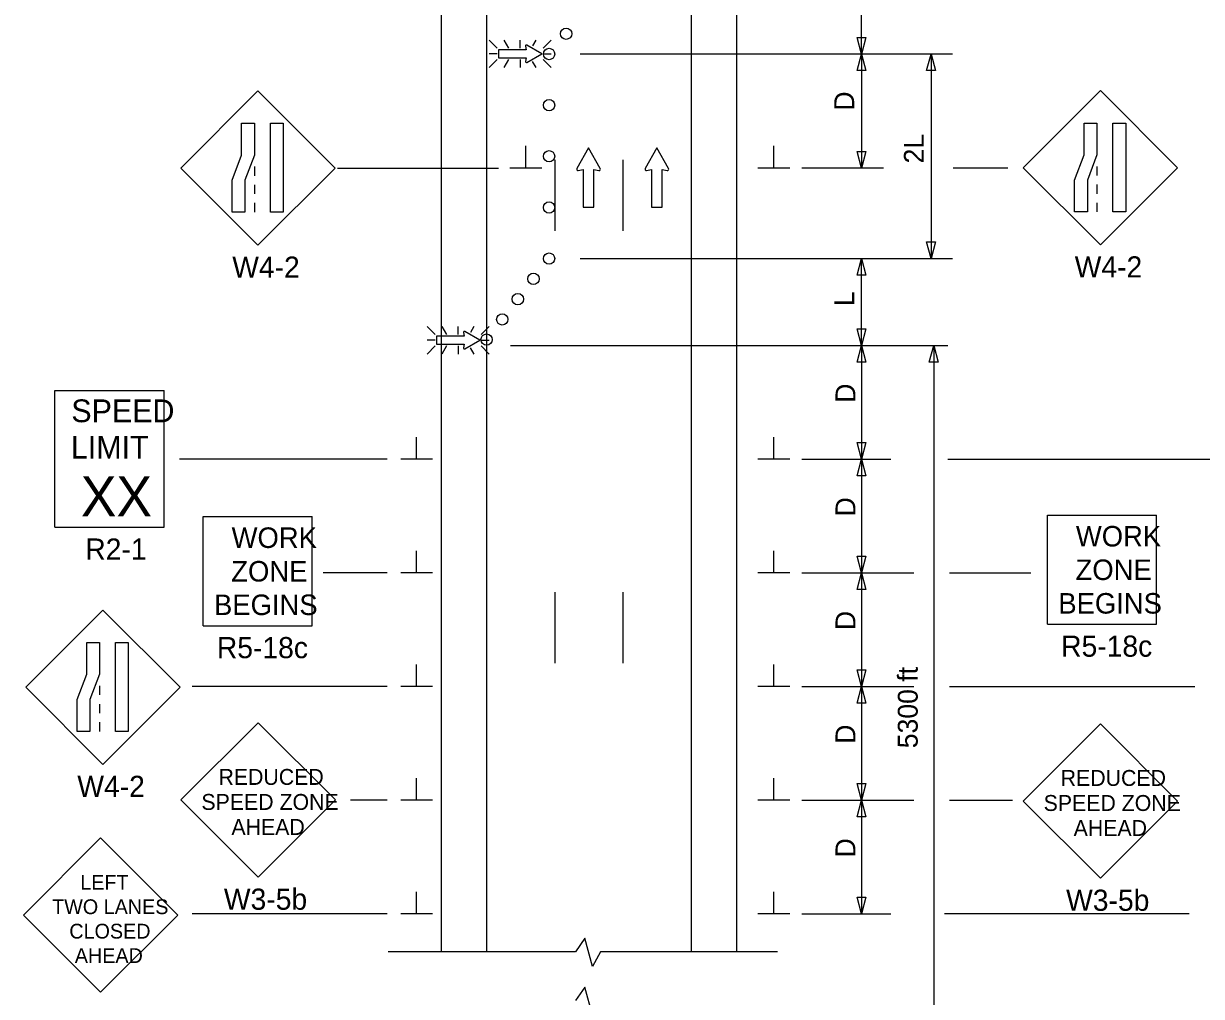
# Model space of a CAD drawing. Extents: x 16590 to 19504, y 5703 to 6974.
# Drawn here: x 17753.9 to 18168.7, y 6275.8 to 6618.1 of the extents above; entities that cross this region are included whole.
import ezdxf

# ---------------------------------------------------------------- set-up
doc = ezdxf.new("R2010")
doc.units = 0
for name, color, linetype in [('ALI_LEGAL_EX', 7, 'Continuous'), ('MT_SCRATCH_LEVEL_E', 7, 'Continuous'), ('PAVT_EDGE_EX', 7, 'Continuous'), ('TRAFFIC_SIGNS_PR', 7, 'Continuous'), ('TYPICAL_TEXT_DIMEN_PR', 7, 'Continuous')]:
    doc.layers.add(name, color=color, linetype=linetype)

msp = doc.modelspace()

# ---------------------------------------------------------------- linework, layer by layer
at = {"layer": 'ALI_LEGAL_EX'}
for points in [[(17940.96, 6570.12), (17940.96, 6545.12)], [(17964.96, 6570.12), (17964.96, 6545.12)], [(17940.96, 6418.06), (17940.96, 6393.06)], [(17964.96, 6418.06), (17964.96, 6393.06)]]:
    msp.add_lwpolyline(points, dxfattribs=at)
at = {"layer": 'MT_SCRATCH_LEVEL_E'}
for p, q in [((17952.86, 6574.33), (17948.75, 6567.09)), ((17957.01, 6567.09), (17952.86, 6574.33)), ((17976.91, 6574.33), (17972.8, 6567.09)), ((17981.06, 6567.09), (17976.91, 6574.33)), ((17949.23, 6566.4), (17951.01, 6566.72)), ((17951.01, 6566.72), (17951.01, 6553.46)), ((17954.75, 6553.46), (17954.75, 6566.72)), ((17954.75, 6566.72), (17956.53, 6566.4)), ((17973.28, 6566.4), (17975.06, 6566.72)), ((17975.06, 6566.72), (17975.06, 6553.46)), ((17978.8, 6553.46), (17978.8, 6566.72)), ((17978.8, 6566.72), (17980.58, 6566.4)), ((17951.01, 6553.46), (17954.75, 6553.46)), ((17975.06, 6553.46), (17978.8, 6553.46))]:
    msp.add_line(p, q, dxfattribs=at)
for centre, start, end in [((17949.16, 6566.86), 150.4248, 279.9638), ((17956.6, 6566.86), 260.0362, 29.7731), ((17973.21, 6566.86), 150.4248, 279.9638), ((17980.65, 6566.86), 260.0362, 29.7731)]:
    msp.add_arc(centre, 0.463, start, end, dxfattribs=at)
at = {"layer": 'PAVT_EDGE_EX'}
for p, q in [((17900.96, 6925.33), (17900.96, 6504.84)), ((17916.96, 6925.33), (17916.96, 6504.84)), ((17988.96, 6925.33), (17988.96, 6504.84)), ((18004.96, 6925.33), (18004.96, 6504.84)), ((17900.96, 6504.84), (17900.96, 6291.41)), ((17916.96, 6504.84), (17916.96, 6291.41)), ((17988.96, 6504.84), (17988.96, 6291.41)), ((18004.96, 6504.84), (18004.96, 6291.41))]:
    msp.add_line(p, q, dxfattribs=at)
at = {"layer": 'TRAFFIC_SIGNS_PR'}
for p, q in [((17920.73, 6609.5), (17917.91, 6612.32)), ((17923.03, 6612.32), (17924.66, 6609.5)), ((17928.82, 6609.5), (17928.82, 6612.32)), ((17934.29, 6612.32), (17933.08, 6610.23)), ((17939.72, 6612.32), (17936.9, 6609.5)), ((17920.73, 6607.47), (17917.91, 6607.47)), ((17936.9, 6607.47), (17939.72, 6607.47)), ((17920.73, 6605.44), (17917.91, 6602.62)), ((17924.68, 6605.44), (17923.05, 6602.62)), ((17928.82, 6605.44), (17928.82, 6602.62)), ((17933, 6604.8), (17934.26, 6602.62)), ((17939.72, 6602.62), (17936.9, 6605.44)), ((17836.44, 6594.43), (17809.29, 6567.28)), ((17863.59, 6567.28), (17836.44, 6594.43)), ((18133.1, 6594.51), (18105.94, 6567.36)), ((18160.25, 6567.36), (18133.1, 6594.51)), ((17809.29, 6567.28), (17836.44, 6540.13)), ((17835.19, 6567.77), (17835.19, 6564.57)), ((17836.44, 6540.13), (17863.59, 6567.28)), ((18105.94, 6567.36), (18133.1, 6540.2)), ((18131.85, 6567.85), (18131.85, 6564.65)), ((18133.1, 6540.2), (18160.25, 6567.36)), ((17835.19, 6561.37), (17835.19, 6558.17)), ((18131.85, 6561.45), (18131.85, 6558.25)), ((17835.19, 6554.97), (17835.19, 6551.77)), ((18131.85, 6555.05), (18131.85, 6551.85)), ((17898.89, 6508.72), (17896.07, 6511.54)), ((17901.19, 6511.53), (17902.82, 6508.72)), ((17906.98, 6508.72), (17906.98, 6511.53)), ((17912.44, 6511.53), (17911.24, 6509.44)), ((17917.88, 6511.53), (17915.06, 6508.72)), ((17898.89, 6506.68), (17896.07, 6506.68)), ((17898.89, 6504.65), (17896.07, 6501.83)), ((17902.84, 6504.65), (17901.21, 6501.83)), ((17906.98, 6504.65), (17906.98, 6501.83)), ((17911.16, 6504.02), (17912.42, 6501.83)), ((17915.06, 6506.68), (17917.88, 6506.68)), ((17917.88, 6501.83), (17915.06, 6504.65)), ((17764.96, 6488.98), (17803.41, 6488.98)), ((17764.96, 6440.92), (17764.96, 6488.98)), ((17803.41, 6440.92), (17803.41, 6488.98)), ((17817.18, 6406.22), (17817.18, 6444.62)), ((17817.18, 6444.62), (17855.58, 6444.62)), ((17855.58, 6406.22), (17855.58, 6444.62)), ((18114.47, 6406.74), (18114.47, 6445.14)), ((18114.47, 6445.14), (18152.87, 6445.14)), ((18152.87, 6406.74), (18152.87, 6445.14)), ((17764.96, 6440.92), (17803.41, 6440.92)), ((17781.89, 6411.7), (17754.73, 6384.55)), ((17809.04, 6384.55), (17781.89, 6411.7)), ((17817.18, 6406.22), (17855.58, 6406.22)), ((18114.47, 6406.74), (18152.87, 6406.74)), ((17754.73, 6384.55), (17781.89, 6357.4)), ((17780.64, 6385.04), (17780.64, 6381.84)), ((17781.89, 6357.4), (17809.04, 6384.55)), ((17780.64, 6378.64), (17780.64, 6375.44)), ((17780.64, 6372.24), (17780.64, 6369.04)), ((17836.52, 6372.08), (17809.33, 6344.89)), ((17863.7, 6344.89), (17836.52, 6372.08)), ((18133.07, 6371.7), (18105.89, 6344.52)), ((18160.26, 6344.52), (18133.07, 6371.7)), ((17809.33, 6344.89), (17836.52, 6317.7)), ((17836.52, 6317.7), (17863.7, 6344.89)), ((18105.89, 6344.52), (18133.07, 6317.33)), ((18133.07, 6317.33), (18160.26, 6344.52)), ((17781.07, 6331.54), (17753.92, 6304.38)), ((17808.22, 6304.38), (17781.07, 6331.54)), ((17753.92, 6304.38), (17781.07, 6277.23)), ((17781.07, 6277.23), (17808.22, 6304.38))]:
    msp.add_line(p, q, dxfattribs=at)
for points in [[(17930.64, 6610.15), (17930.87, 6608.86), (17921.15, 6608.86), (17921.15, 6606.11), (17930.87, 6606.11), (17930.64, 6604.81)], [(17931.14, 6604.46), (17936.45, 6607.47), (17931.14, 6610.51)], [(17908.8, 6509.36), (17909.03, 6508.07), (17899.31, 6508.07), (17899.31, 6505.32), (17909.03, 6505.32), (17908.8, 6504.02)], [(17909.3, 6503.67), (17914.61, 6506.68), (17909.3, 6509.72)]]:
    msp.add_lwpolyline(points, dxfattribs=at)
for points in [[(17835.19, 6583.02), (17835.19, 6571.83), (17831.85, 6562.95), (17831.85, 6551.77), (17827.36, 6551.77), (17827.36, 6562.95), (17830.7, 6571.83), (17830.7, 6583.02)], [(17845.33, 6583.02), (17845.33, 6551.77), (17840.84, 6551.77), (17840.84, 6583.02)], [(18131.85, 6583.09), (18131.85, 6571.91), (18128.51, 6563.03), (18128.51, 6551.85), (18124.01, 6551.85), (18124.01, 6563.03), (18127.36, 6571.91), (18127.36, 6583.09)], [(18141.99, 6583.09), (18141.99, 6551.85), (18137.49, 6551.85), (18137.49, 6583.09)], [(17780.64, 6400.29), (17780.64, 6389.11), (17777.3, 6380.22), (17777.3, 6369.04), (17772.8, 6369.04), (17772.8, 6380.22), (17776.15, 6389.11), (17776.15, 6400.29)], [(17790.78, 6400.29), (17790.78, 6369.04), (17786.28, 6369.04), (17786.28, 6400.29)]]:
    msp.add_lwpolyline(points, close=True, dxfattribs=at)
for centre in [(17944.96, 6614.54), (17938.96, 6607.4), (17938.96, 6589.4), (17938.96, 6571.4), (17938.96, 6553.4), (17938.96, 6535.4), (17933.46, 6528.27), (17927.96, 6521.14), (17922.47, 6514.01), (17916.97, 6506.89)]:
    msp.add_circle(centre, 2, dxfattribs=at)
for centre, start, end in [((17930.98, 6610.21), 61.4833, 189.9593), ((17930.98, 6604.76), 170.7308, 298.8916), ((17909.14, 6509.42), 61.4833, 189.9593), ((17909.14, 6503.97), 170.7308, 298.8916)]:
    msp.add_arc(centre, 0.341, start, end, dxfattribs=at)
at = {"layer": 'TYPICAL_TEXT_DIMEN_PR'}
for p, q in [((18048.96, 6607.4), (18048.96, 6637.96)), ((18048.96, 6607.4), (18047.39, 6613.26)), ((18047.39, 6613.26), (18048.96, 6613.26)), ((18048.96, 6613.26), (18050.53, 6613.26)), ((18050.53, 6613.26), (18048.96, 6607.4)), ((18081, 6607.4), (17949.86, 6607.4)), ((18047.39, 6601.54), (18048.96, 6607.4)), ((18048.96, 6607.4), (18048.96, 6567.27)), ((18048.96, 6607.4), (18050.53, 6601.54)), ((18071.9, 6601.54), (18073.47, 6607.4)), ((18073.47, 6607.4), (18075.04, 6601.54)), ((18073.47, 6607.4), (18073.47, 6535.4)), ((18048.96, 6601.54), (18047.39, 6601.54)), ((18050.53, 6601.54), (18048.96, 6601.54)), ((18073.47, 6601.54), (18071.9, 6601.54)), ((18075.04, 6601.54), (18073.47, 6601.54)), ((17930.81, 6567.27), (17930.81, 6575.06)), ((18018.08, 6567.27), (18018.08, 6575.06)), ((18048.96, 6567.27), (18047.39, 6573.13)), ((18047.39, 6573.13), (18048.96, 6573.13)), ((18048.96, 6573.13), (18050.53, 6573.13)), ((18050.53, 6573.13), (18048.96, 6567.27)), ((17864.45, 6567.27), (17921.15, 6567.27)), ((17936.43, 6567.27), (17925.18, 6567.27)), ((18023.71, 6567.27), (18012.46, 6567.27)), ((18056.71, 6567.27), (18027.96, 6567.27)), ((18100.5, 6567.27), (18081.25, 6567.27)), ((18073.47, 6562.27), (18073.47, 6558.5)), ((18073.47, 6535.4), (18071.9, 6541.26)), ((18071.9, 6541.26), (18073.47, 6541.26)), ((18073.47, 6541.26), (18075.04, 6541.26)), ((18075.04, 6541.26), (18073.47, 6535.4)), ((17949.86, 6535.4), (18081, 6535.4)), ((18047.39, 6529.54), (18048.96, 6535.4)), ((18048.96, 6504.84), (18048.96, 6535.4)), ((18048.96, 6535.4), (18050.53, 6529.54)), ((18048.96, 6529.54), (18047.39, 6529.54)), ((18050.53, 6529.54), (18048.96, 6529.54)), ((18048.96, 6504.84), (18047.39, 6510.7)), ((18047.39, 6510.7), (18048.96, 6510.7)), ((18048.96, 6510.7), (18050.53, 6510.7)), ((18050.53, 6510.7), (18048.96, 6504.84)), ((17925.35, 6504.84), (18079.39, 6504.84)), ((17925.35, 6504.84), (18079.39, 6504.84)), ((18047.39, 6498.97), (18048.96, 6504.84)), ((18048.96, 6504.84), (18048.96, 6464.84)), ((18048.96, 6504.84), (18050.53, 6498.97)), ((18072.82, 6498.97), (18074.39, 6504.84)), ((18074.39, 6504.84), (18075.96, 6498.97)), ((18074.39, 6504.84), (18074.39, 6229.16)), ((18048.96, 6498.97), (18047.39, 6498.97)), ((18050.53, 6498.97), (18048.96, 6498.97)), ((18074.39, 6498.97), (18072.82, 6498.97)), ((18075.96, 6498.97), (18074.39, 6498.97)), ((17892.33, 6464.83), (17892.33, 6472.61)), ((18018.08, 6464.83), (18018.08, 6472.61)), ((18048.96, 6464.84), (18047.39, 6470.7)), ((18047.39, 6470.7), (18048.96, 6470.7)), ((18048.96, 6470.7), (18050.53, 6470.7)), ((18050.53, 6470.7), (18048.96, 6464.84)), ((17881.91, 6464.84), (17808.8, 6464.84)), ((17897.96, 6464.83), (17886.71, 6464.83)), ((18023.71, 6464.83), (18012.46, 6464.83)), ((18027.96, 6464.84), (18059.27, 6464.84)), ((18047.39, 6458.97), (18048.96, 6464.84)), ((18048.96, 6464.84), (18048.96, 6424.84)), ((18048.96, 6464.84), (18050.53, 6458.97)), ((18079.39, 6464.84), (18174.5, 6464.84)), ((18048.96, 6458.97), (18047.39, 6458.97)), ((18050.53, 6458.97), (18048.96, 6458.97)), ((17892.33, 6424.83), (17892.33, 6432.61)), ((18018.08, 6424.83), (18018.08, 6432.61)), ((18048.96, 6424.84), (18047.39, 6430.7)), ((18047.39, 6430.7), (18048.96, 6430.7)), ((18048.96, 6430.7), (18050.53, 6430.7)), ((18050.53, 6430.7), (18048.96, 6424.84)), ((17881.91, 6424.84), (17859.38, 6424.84)), ((17897.96, 6424.83), (17886.71, 6424.83)), ((18023.71, 6424.83), (18012.46, 6424.83)), ((18027.96, 6424.84), (18067.4, 6424.84)), ((18047.39, 6418.97), (18048.96, 6424.84)), ((18048.96, 6424.84), (18048.96, 6384.84)), ((18048.96, 6424.84), (18050.53, 6418.97)), ((18079.94, 6424.84), (18108.56, 6424.84)), ((18048.96, 6418.97), (18047.39, 6418.97)), ((18050.53, 6418.97), (18048.96, 6418.97)), ((17892.33, 6384.83), (17892.33, 6392.61)), ((18018.08, 6384.83), (18018.08, 6392.61)), ((18048.96, 6384.84), (18047.39, 6390.7)), ((18047.39, 6390.7), (18048.96, 6390.7)), ((18048.96, 6390.7), (18050.53, 6390.7)), ((18050.53, 6390.7), (18048.96, 6384.84)), ((17881.91, 6384.84), (17813.3, 6384.84)), ((17897.96, 6384.83), (17886.71, 6384.83)), ((18023.71, 6384.83), (18012.46, 6384.83)), ((18027.96, 6384.84), (18067.4, 6384.84)), ((18047.39, 6378.97), (18048.96, 6384.84)), ((18048.96, 6384.84), (18048.96, 6344.84)), ((18048.96, 6384.84), (18050.53, 6378.97)), ((18079.94, 6384.84), (18166.36, 6384.84)), ((18048.96, 6378.97), (18047.39, 6378.97)), ((18050.53, 6378.97), (18048.96, 6378.97)), ((17892.33, 6344.83), (17892.33, 6352.61)), ((18018.08, 6344.83), (18018.08, 6352.61)), ((18048.96, 6344.84), (18047.39, 6350.7)), ((18047.39, 6350.7), (18048.96, 6350.7)), ((18048.96, 6350.7), (18050.53, 6350.7)), ((18050.53, 6350.7), (18048.96, 6344.84)), ((17881.91, 6344.84), (17869.02, 6344.84)), ((17897.96, 6344.83), (17886.71, 6344.83)), ((18023.71, 6344.83), (18012.46, 6344.83)), ((18027.96, 6344.84), (18067.4, 6344.84)), ((18047.39, 6338.97), (18048.96, 6344.84)), ((18048.96, 6344.84), (18048.96, 6304.84)), ((18048.96, 6344.84), (18050.53, 6338.97)), ((18079.94, 6344.84), (18102.1, 6344.84)), ((18048.96, 6338.97), (18047.39, 6338.97)), ((18050.53, 6338.97), (18048.96, 6338.97)), ((17892.33, 6304.83), (17892.33, 6312.61)), ((18018.08, 6304.83), (18018.08, 6312.61)), ((18048.96, 6304.84), (18047.39, 6310.7)), ((18047.39, 6310.7), (18048.96, 6310.7)), ((18048.96, 6310.7), (18050.53, 6310.7)), ((18050.53, 6310.7), (18048.96, 6304.84)), ((17881.91, 6304.84), (17813.3, 6304.84)), ((17897.96, 6304.83), (17886.71, 6304.83)), ((18023.71, 6304.83), (18012.46, 6304.83)), ((18027.96, 6304.84), (18059.27, 6304.84)), ((18164.29, 6304.84), (18078.14, 6304.84)), ((17951.56, 6296.21), (17948.31, 6291.41)), ((17954.3, 6286.27), (17951.56, 6296.21)), ((17948.31, 6291.41), (17882.36, 6291.41)), ((17957.05, 6291.41), (17954.3, 6286.27)), ((18019.38, 6291.41), (17957.05, 6291.41)), ((17951.56, 6279.07), (17948.31, 6274.27)), ((17954.3, 6269.13), (17951.56, 6279.07))]:
    msp.add_line(p, q, dxfattribs=at)

# ---------------------------------------------------------------- texts
at = {"layer": 'TRAFFIC_SIGNS_PR'}
for s, height, p in [('W4-2', 7.44, (17827.4, 6528.69)), ('W4-2', 7.44, (18124.05, 6528.76)), ('SPEED', 8.01, (17770.74, 6477.83)), ('LIMIT', 8.01, (17770.58, 6465.01)), ('XX', 14.048, (17774.09, 6444.68)), ('WORK', 7.217, (18124.46, 6434.1)), ('R2-1', 7.449, (17775.65, 6429.46)), ('WORK', 7.217, (17827.18, 6433.58)), ('ZONE', 7.217, (17827.06, 6421.77)), ('ZONE', 7.217, (18124.35, 6422.29)), ('BEGINS', 7.217, (17820.99, 6409.96)), ('BEGINS', 7.217, (18118.28, 6410.48)), ('R5-18c', 7.44, (17821.99, 6394.78)), ('R5-18c', 7.44, (18119.28, 6395.3)), ('REDUCED', 5.607, (17822.55, 6350.2)), ('REDUCED', 5.607, (18119.11, 6349.83)), ('W4-2', 7.44, (17772.85, 6345.96)), ('SPEED ZONE', 5.607, (17816.54, 6341.39)), ('SPEED ZONE', 5.607, (18113.1, 6341.02)), ('AHEAD', 5.607, (17827.11, 6332.58)), ('AHEAD', 5.607, (18123.67, 6332.21)), ('LEFT', 5.2, (17773.88, 6313.32)), ('W3-5b', 7.449, (17824.45, 6306.25)), ('W3-5b', 7.449, (18121.01, 6305.88)), ('TWO LANES', 5.2, (17763.98, 6304.72)), ('CLOSED', 5.2, (17770.03, 6296.12)), ('AHEAD', 5.2, (17771.96, 6287.52))]:
    msp.add_text(s, height=height, dxfattribs=at).set_placement(p)
at = {"layer": 'TYPICAL_TEXT_DIMEN_PR'}
for s, p in [('D', (18046.4, 6587.46)), ('2L', (18070.91, 6568.9)), ('L', (18046.4, 6518.69)), ('D', (18046.8, 6484.65)), ('D', (18046.8, 6444.65)), ('D', (18046.8, 6404.65)), ('5300 ft', (18068.76, 6363.08)), ('D', (18046.8, 6364.65)), ('D', (18046.8, 6324.65))]:
    msp.add_text(s, height=7, rotation=90, dxfattribs=at).set_placement(p)

doc.saveas('drawing.dxf')
